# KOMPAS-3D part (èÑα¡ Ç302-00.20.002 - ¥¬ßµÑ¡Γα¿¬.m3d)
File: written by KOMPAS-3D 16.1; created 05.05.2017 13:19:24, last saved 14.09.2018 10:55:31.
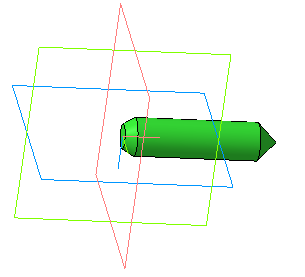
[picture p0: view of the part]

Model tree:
1. Эскиз:1
2. Операция вращения:2
     Угол 1 = 360
3. Фаска:3  (labels: Сталь 40Х  ГОСТ 4543-71)
     Угол = 30; Длина 1 = 3; Длина 2 = 1.73205

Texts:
  Линейный размер с обрывом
